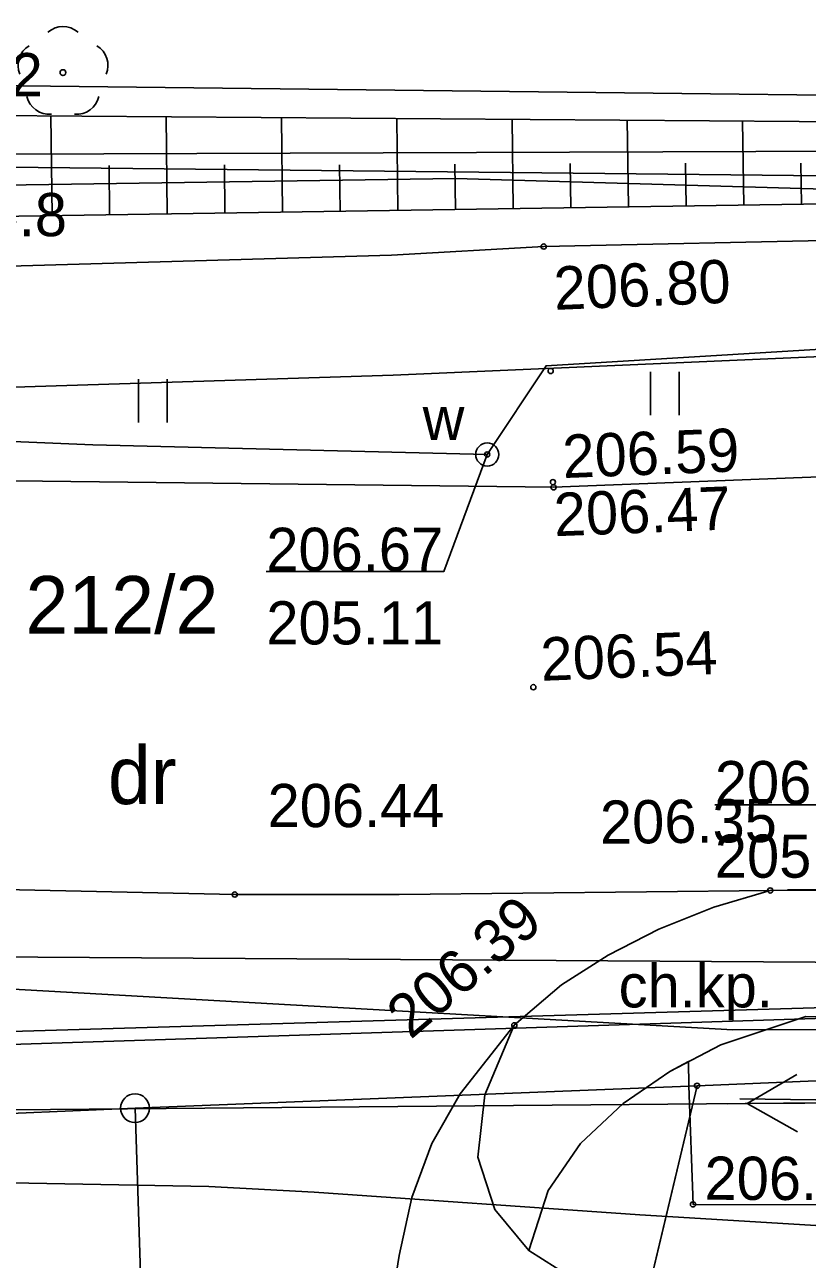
# Model space of a CAD drawing. Extents: x 6512400 to 6513200, y 6022500 to 6022750.
# Drawn here: x 6512733.85 to 6512747.42, y 6022670.32 to 6022691.75 of the extents above; entities that cross this region are included whole.
import ezdxf

# ---------------------------------------------------------------- set-up
doc = ezdxf.new("R2010")
doc.units = 0
for name, color, linetype in [('202-punkt graniczny', 7, 'Continuous'), ('203-punkt graniczny', 7, 'Continuous'), ('210-oznaczenie konturu użytku gruntowego', 7, 'Continuous'), ('211-numer działki ewidencyjnej', 7, 'Continuous'), ('216-obręb ewidencyjny', 7, 'Continuous'), ('218-kontur użytku gruntowego', 7, 'Continuous'), ('219-działka ewidencyjna', 7, 'Continuous'), ('820-Skarpa nieumocniona', 7, 'Continuous'), ('823-Szczyt skarpy nieumocninej', 7, 'Continuous'), ('824-Podnóże skarpy nieumocninej', 7, 'Continuous'), ('903-Żywopłot', 7, 'Continuous'), ('940-Trawnik symb. poj.', 7, 'Continuous'), ('chodnik', 7, 'Continuous'), ('chodnik (powierzchnia)', 7, 'Continuous'), ('chodnik (powierzchnia)-Atr17', 7, 'Continuous'), ('drzewo liściaste (punkt)', 7, 'Continuous'), ('inny obiekt zagospodarowania terenu', 7, 'Continuous'), ('jezdnia (powierzchnia)', 7, 'Continuous'), ('krawężnik (linia)', 7, 'Continuous'), ('przewód elektroenergetyczny (linia)', 7, 'Continuous'), ('przewód elektroenergetyczny niskiego napięcia (linia)', 7, 'Continuous'), ('przewód elektroenergetyczny niskiego napięcia (linia) - symbol', 7, 'Continuous'), ('przewód kanalizacyjny (linia)', 7, 'Continuous'), ('przewód telekomunikacyjny (linia)', 7, 'Continuous'), ('przewód wodociągowy (linia)', 7, 'Continuous'), ('punkt o określonej wysokości (sieć kanalizacyjna)-Atr2', 7, 'Continuous'), ('punkt o określonej wysokości (sieć kanalizacyjna)-Atr3', 7, 'Continuous'), ('punkt o określonej wysokości (sieć wodociągowa)', 7, 'Continuous'), ('punkt o określonej wysokości (sieć wodociągowa)-Atr2', 7, 'Continuous'), ('punkt o określonej wysokości (sieć wodociągowa)-Atr3', 7, 'Continuous'), ('punkt wysokościowy naturalny-Atr2', 7, 'Continuous'), ('punkt wysokościowy sztuczny', 7, 'Continuous'), ('punkt wysokościowy sztuczny-Atr2', 7, 'Continuous'), ('zasuwa - siec wodociągowa (punkt)', 7, 'Continuous'), ('zasuwa - siec wodociągowa (punkt)-Atr17', 7, 'Continuous')]:
    doc.layers.add(name, color=color, linetype=linetype)

# ---------------------------------------------------------------- blocks, each defined once
blk = doc.blocks.new('203')
blk.add_circle((0, 0), 0.045)
blk = doc.blocks.new('202')
blk.add_circle((0, 0), 0.25)
blk = doc.blocks.new('OP021')
blk.add_circle((0, 0), 0.05)
for centre, start, end in [((0, 0.4), 49.272, 130.728), ((-0.38, 0.124), 121.308, 202.548), ((0.38, 0.124), 337.452, 58.692), ((-0.235, -0.324), 193.221, 274.871), ((0.235, -0.324), 265.129, 346.779)]:
    blk.add_arc(centre, 0.4, start, end)
blk = doc.blocks.new('940P')
for p, q in [((-0.25, -0.375), (-0.25, 0.375)), ((0.25, -0.375), (0.25, 0.375))]:
    blk.add_line(p, q)
blk = doc.blocks.new('PW01')
blk.add_circle((0, 0), 0.045)
blk = doc.blocks.new('US25')
blk.add_circle((0, 0), 0.2)
blk = doc.blocks.new('PW02')
blk.add_circle((0, 0), 0.045)
blk = doc.blocks.new('PE04')
for p, q in [((4.65, 0), (3.784, 0.5)), ((0.65, 0), (0, 0)), ((0.65, 0), (1.65, 0)), ((1.65, 0), (2.65, 0)), ((2.65, 0), (3.65, 0)), ((3.65, 0), (4.65, 0)), ((4.65, 0), (3.784, -0.5)), ((4.65, 0), (5, 0))]:
    blk.add_line(p, q)

msp = doc.modelspace()

# ---------------------------------------------------------------- linework, layer by layer
at = {"layer": '216-obręb ewidencyjny'}
for points in [[(6512688.62, 6022674.91), (6512702.58, 6022674.18), (6512725.78, 6022672.95), (6512730.35, 6022672.71), (6512735.76, 6022672.94), (6512745.51, 6022673.33), (6512754.87, 6022673.72), (6512768.24, 6022674.27), (6512785.56, 6022674.74), (6512790.49, 6022674.74), (6512796.96, 6022674.74), (6512801.96, 6022670.34), (6512828.67, 6022670.98), (6512833.61, 6022675.02), (6512836.69, 6022675.17), (6512851.94, 6022675.93)], [(6512785.56, 6022674.74), (6512768.24, 6022674.27), (6512754.87, 6022673.72), (6512745.51, 6022673.33), (6512735.76, 6022672.94), (6512730.35, 6022672.71), (6512725.78, 6022672.95), (6512702.575, 6022674.177)]]:
    msp.add_lwpolyline(points, dxfattribs=at)
at = {"layer": '218-kontur użytku gruntowego'}
for points in [[(6512706.4, 6022691.01), (6512787.08, 6022690.07)], [(6512787.08, 6022690.07), (6512706.4, 6022691.01)], [(6512754.87, 6022673.72), (6512745.51, 6022673.33)], [(6512745.51, 6022673.33), (6512754.87, 6022673.72)], [(6512745.51, 6022673.33), (6512735.76, 6022672.94)], [(6512735.76, 6022672.94), (6512745.51, 6022673.33)], [(6512745.51, 6022673.33), (6512741.4, 6022656.05)], [(6512741.4, 6022656.05), (6512745.51, 6022673.33)], [(6512735.76, 6022672.94), (6512730.35, 6022672.71)], [(6512730.35, 6022672.71), (6512735.76, 6022672.94)], [(6512735.76, 6022672.94), (6512736.07, 6022663.44)], [(6512736.07, 6022663.44), (6512735.76, 6022672.94)]]:
    msp.add_lwpolyline(points, dxfattribs=at)
at = {"layer": '219-działka ewidencyjna'}
for points in [[(6512706.4, 6022691.01), (6512787.08, 6022690.07)], [(6512754.87, 6022673.72), (6512745.51, 6022673.33)], [(6512745.51, 6022673.33), (6512735.76, 6022672.94)], [(6512745.51, 6022673.33), (6512739.15, 6022646.62)], [(6512730.35, 6022672.71), (6512735.76, 6022672.94)], [(6512735.76, 6022672.94), (6512736.07, 6022663.44)]]:
    msp.add_lwpolyline(points, dxfattribs=at)
at = {"layer": '820-Skarpa nieumocniona'}
for p, q in [((6512734.32, 6022688.44), (6512734.3, 6022690.17)), ((6512736.32, 6022688.47), (6512736.3, 6022690.16)), ((6512738.32, 6022688.5), (6512738.3, 6022690.14)), ((6512740.32, 6022688.53), (6512740.3, 6022690.13)), ((6512742.32, 6022688.56), (6512742.3, 6022690.11)), ((6512744.32, 6022688.59), (6512744.3, 6022690.1)), ((6512746.32, 6022688.62), (6512746.3, 6022690.08)), ((6512735.32, 6022688.45), (6512735.31, 6022689.31)), ((6512737.32, 6022688.48), (6512737.31, 6022689.32)), ((6512739.32, 6022688.51), (6512739.31, 6022689.32)), ((6512741.32, 6022688.54), (6512741.31, 6022689.33)), ((6512743.32, 6022688.57), (6512743.31, 6022689.34)), ((6512745.32, 6022688.6), (6512745.31, 6022689.35)), ((6512747.32, 6022688.63), (6512747.31, 6022689.35))]:
    msp.add_line(p, q, dxfattribs=at)
at = {"layer": '823-Szczyt skarpy nieumocninej'}
msp.add_lwpolyline([(6512754.81, 6022689.02), (6512750.38, 6022688.68), (6512731.85, 6022688.4), (6512721.27, 6022688.58), (6512714.51, 6022690.92)], dxfattribs=at)
at = {"layer": '824-Podnóże skarpy nieumocninej'}
msp.add_lwpolyline([(6512714.51, 6022690.92), (6512719.59, 6022690.77), (6512731.72, 6022690.19), (6512750.39, 6022690.05), (6512754.81, 6022689.02)], dxfattribs=at)
at = {"layer": '903-Żywopłot'}
msp.add_lwpolyline([(6512750.46, 6022689.1), (6512732.44, 6022689.29)], dxfattribs=at)
at = {"layer": 'chodnik'}
msp.add_lwpolyline([(6512768.44, 6022668.05), (6512768.21, 6022674.06), (6512768.22, 6022675.69), (6512769.23, 6022676.77), (6512761.81, 6022676.79), (6512762.96, 6022675.7), (6512762.9, 6022674.52), (6512762.83, 6022671.34), (6512755.26, 6022671.25), (6512745.44, 6022671.27), (6512745.37, 6022673.33), (6512745.36, 6022673.75), (6512745.04, 6022673.58), (6512744.23, 6022673.02), (6512743.49, 6022672.33), (6512742.93, 6022671.51), (6512742.59, 6022670.47), (6512743.54, 6022669.87)], dxfattribs=at)
at = {"layer": 'chodnik (powierzchnia)'}
for points in [[(6512786.39, 6022689.96), (6512786.43, 6022689.56), (6512785.75, 6022688.59), (6512780.55, 6022688.53), (6512773.92, 6022688.46), (6512772.96, 6022688.47), (6512771.38, 6022688.54), (6512759.61, 6022688.41), (6512758.59, 6022688.29), (6512753.64, 6022688.13), (6512742.85, 6022687.9), (6512740.21, 6022687.75), (6512727.76, 6022687.39)], [(6512770.26, 6022685.56), (6512768.81, 6022686.87), (6512761.83, 6022686.62), (6512760.89, 6022686.7), (6512759.88, 6022686.67), (6512758.73, 6022686.47), (6512753.37, 6022686.24), (6512740.24, 6022685.67), (6512727.63, 6022685.27)], [(6512747.4, 6022674.53), (6512745.92, 6022674.04), (6512745.04, 6022673.58), (6512744.23, 6022673.02), (6512743.49, 6022672.33), (6512742.93, 6022671.51), (6512742.59, 6022670.47), (6512742, 6022671.18), (6512741.71, 6022672.09), (6512741.83, 6022673.17), (6512742.34, 6022674.38), (6512743.16, 6022675.08), (6512743.97, 6022675.6), (6512744.85, 6022676.05), (6512745.8, 6022676.43), (6512746.78, 6022676.72)], [(6512747.08, 6022676.73), (6512757.48, 6022676.77), (6512761.81, 6022676.79), (6512762.96, 6022675.7), (6512762.9, 6022674.52), (6512757.26, 6022674.48), (6512747.4, 6022674.53)]]:
    msp.add_lwpolyline(points, dxfattribs=at)
at = {"layer": 'inny obiekt zagospodarowania terenu'}
msp.add_lwpolyline([(6512746.25, 6022673.1), (6512762.53, 6022672.89)], dxfattribs=at)
at = {"layer": 'jezdnia (powierzchnia)'}
for points in [[(6512707.74, 6022685), (6512715.41, 6022684.53), (6512729.72, 6022683.88), (6512743.02, 6022683.72), (6512757.15, 6022684.27)], [(6512707.08, 6022677.87), (6512714.85, 6022677.5), (6512727.62, 6022676.91), (6512733.49, 6022676.74), (6512737.49, 6022676.65), (6512740.34, 6022676.65), (6512746.78, 6022676.72), (6512757.48, 6022676.77)], [(6512740.11, 6022668.94), (6512740.34, 6022670.38), (6512740.56, 6022671.39), (6512740.91, 6022672.33), (6512741.4, 6022673.19), (6512742.34, 6022674.38), (6512743.16, 6022675.08), (6512743.97, 6022675.6), (6512744.85, 6022676.05), (6512745.8, 6022676.43), (6512746.78, 6022676.72), (6512740.34, 6022676.65), (6512737.49, 6022676.65), (6512733.49, 6022676.74)]]:
    msp.add_lwpolyline(points, dxfattribs=at)
at = {"layer": 'krawężnik (linia)'}
for points in [[(6512757.15, 6022684.27), (6512743.02, 6022683.72), (6512729.72, 6022683.88), (6512715.41, 6022684.53), (6512707.74, 6022685)], [(6512707.08, 6022677.87), (6512714.85, 6022677.5), (6512727.62, 6022676.91), (6512733.49, 6022676.74), (6512737.49, 6022676.65), (6512740.34, 6022676.65), (6512746.78, 6022676.72), (6512757.48, 6022676.77)], [(6512733.49, 6022676.74), (6512737.49, 6022676.65), (6512740.34, 6022676.65), (6512746.78, 6022676.72), (6512745.8, 6022676.43), (6512744.85, 6022676.05), (6512743.97, 6022675.6), (6512743.16, 6022675.08), (6512742.34, 6022674.38), (6512741.4, 6022673.19), (6512740.91, 6022672.33), (6512740.56, 6022671.39), (6512740.34, 6022670.38), (6512740.11, 6022668.94)]]:
    msp.add_lwpolyline(points, dxfattribs=at)
msp.add_lwpolyline([(6512742.34, 6022674.38), (6512741.83, 6022673.17), (6512741.71, 6022672.09), (6512742, 6022671.18), (6512742.59, 6022670.47), (6512743.54, 6022669.87), (6512744.61, 6022669.47), (6512743.66, 6022665.57), (6512742.75, 6022665.44), (6512741.78, 6022665.16), (6512740.87, 6022664.67), (6512740.14, 6022663.96), (6512739.53, 6022663.03), (6512739.77, 6022665.13), (6512739.93, 6022667.1), (6512740.11, 6022668.94), (6512740.34, 6022670.38), (6512740.56, 6022671.39), (6512740.91, 6022672.33), (6512741.4, 6022673.19)], close=True, dxfattribs=at)
at = {"layer": 'przewód elektroenergetyczny (linia)'}
for points in [[(6512731.37, 6022676.71), (6512731.37, 6022675.58), (6512748.46, 6022675.47), (6512780.13, 6022675.56), (6512787.87, 6022675.5)], [(6512702.569, 6022673.878), (6512710.28, 6022673.25), (6512716.66, 6022675.97), (6512746.13, 6022674.3), (6512752.79, 6022674.32), (6512760.61, 6022675.35), (6512763.38, 6022676.06), (6512798.79, 6022676.04)], [(6512702.603, 6022675.567), (6512731.84, 6022674.22), (6512765.79, 6022675.22), (6512787.87, 6022675.5)]]:
    msp.add_lwpolyline(points, dxfattribs=at)
at = {"layer": 'przewód elektroenergetyczny niskiego napięcia (linia)'}
for points in [[(6512782.09, 6022689.68), (6512702.887, 6022689.392)], [(6512702.887, 6022689.392), (6512782.09, 6022689.68)], [(6512719.56, 6022672.79), (6512751.03, 6022673.06)]]:
    msp.add_lwpolyline(points, dxfattribs=at)
at = {"layer": 'przewód kanalizacyjny (linia)'}
msp.add_lwpolyline([(6512716.83, 6022672.25), (6512720.83, 6022672.11), (6512730.47, 6022671.7), (6512737.04, 6022671.58), (6512738.87, 6022671.48), (6512744.52, 6022671.09), (6512750.15, 6022670.75), (6512752.63, 6022670.67), (6512753.2, 6022670.48)], dxfattribs=at)
at = {"layer": 'przewód telekomunikacyjny (linia)'}
msp.add_lwpolyline([(6512786.53, 6022688.5), (6512773.43, 6022688.9), (6512751.33, 6022688.79), (6512741.32, 6022689.08), (6512718.97, 6022688.75), (6512713.12, 6022690.07), (6512711.25, 6022690.1), (6512706.82, 6022689.08), (6512704.98, 6022689.07)], dxfattribs=at)
at = {"layer": 'przewód wodociągowy (linia)'}
for points in [[(6512777.27, 6022686.75), (6512776.94, 6022686.76), (6512762.32, 6022687.01), (6512742.89, 6022685.83), (6512741.87, 6022684.29)], [(6512702.822, 6022686.219), (6512712.1, 6022685.41), (6512735.03, 6022684.46), (6512741.87, 6022684.29)], [(6512702.579, 6022674.359), (6512731.63, 6022673.98), (6512765.81, 6022675.09), (6512780.05, 6022675.09), (6512787.64, 6022675.26)]]:
    msp.add_lwpolyline(points, dxfattribs=at)
at = {"layer": 'punkt o określonej wysokości (sieć kanalizacyjna)-Atr2'}
msp.add_lwpolyline([(6512750.37, 6022677.15), (6512748.96, 6022678.21), (6512745.819, 6022678.21)], dxfattribs=at)
at = {"layer": 'punkt o określonej wysokości (sieć wodociągowa)-Atr2'}
msp.add_lwpolyline([(6512741.87, 6022684.29), (6512741.12, 6022682.26), (6512738.038, 6022682.26)], dxfattribs=at)

# ---------------------------------------------------------------- block references
at = {"layer": '202-punkt graniczny'}
msp.add_blockref('202', (6512735.76, 6022672.94), dxfattribs=at)
at = {"layer": '203-punkt graniczny'}
msp.add_blockref('203', (6512745.51, 6022673.33), dxfattribs=at)
at = {"layer": '940-Trawnik symb. poj.'}
for p in [(6512744.95, 6022685.35), (6512736.07, 6022685.22)]:
    msp.add_blockref('940P', p, dxfattribs=at)
at = {"layer": 'drzewo liściaste (punkt)'}
msp.add_blockref('OP021', (6512734.51, 6022690.92), dxfattribs=at)
at = {"layer": 'przewód elektroenergetyczny niskiego napięcia (linia) - symbol', "rotation": -179.50800000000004}
msp.add_blockref('PE04', (6512751.03, 6022673.06), dxfattribs=at)
at = {"layer": 'punkt o określonej wysokości (sieć wodociągowa)'}
msp.add_blockref('PW01', (6512742.97, 6022685.74), dxfattribs=at)
at = {"layer": 'punkt o określonej wysokości (sieć wodociągowa)', "rotation": -0.586}
msp.add_blockref('PW01', (6512741.87, 6022684.29), dxfattribs=at)
at = {"layer": 'punkt wysokościowy sztuczny'}
for p in [(6512742.85, 6022687.9), (6512743.01, 6022683.81), (6512743.02, 6022683.72), (6512742.67, 6022680.25), (6512737.49, 6022676.65), (6512746.78, 6022676.72), (6512742.34, 6022674.38), (6512745.44, 6022671.27)]:
    msp.add_blockref('PW02', p, dxfattribs=at)
at = {"layer": 'zasuwa - siec wodociągowa (punkt)', "rotation": -0.586}
msp.add_blockref('US25', (6512741.87, 6022684.29), dxfattribs=at)

# ---------------------------------------------------------------- texts
at = {"layer": '210-oznaczenie konturu użytku gruntowego'}
msp.add_text('dr', height=1, dxfattribs=at).set_placement((6512735.29, 6022678.22))
at = {"layer": '211-numer działki ewidencyjnej'}
msp.add_text('212/2', height=1, dxfattribs=at).set_placement((6512733.86, 6022681.18))
at = {"layer": 'chodnik (powierzchnia)-Atr17'}
msp.add_text('ch.kp.', height=0.75, dxfattribs=at).set_placement((6512744.15, 6022674.69))
at = {"layer": 'punkt o określonej wysokości (sieć kanalizacyjna)-Atr2'}
msp.add_text('206.36', height=0.75, dxfattribs=at).set_placement((6512745.819, 6022678.218))
at = {"layer": 'punkt o określonej wysokości (sieć kanalizacyjna)-Atr3'}
msp.add_text('205.49', height=0.75, dxfattribs=at).set_placement((6512745.819, 6022676.942))
at = {"layer": 'punkt o określonej wysokości (sieć wodociągowa)-Atr2'}
msp.add_text('206.67', height=0.75, dxfattribs=at).set_placement((6512738.038, 6022682.268))
at = {"layer": 'punkt o określonej wysokości (sieć wodociągowa)-Atr3'}
msp.add_text('205.11', height=0.75, dxfattribs=at).set_placement((6512738.038, 6022680.992))
at = {"layer": 'punkt wysokościowy naturalny-Atr2'}
for s, p in [('206.2', (6512731.65, 6022690.51)), ('206.8', (6512732.07, 6022688.08))]:
    msp.add_text(s, height=0.75, dxfattribs=at).set_placement(p)
at = {"layer": 'punkt wysokościowy sztuczny-Atr2'}
for s, rotation, p in [('206.80', 2.382, (6512743.04, 6022686.8)), ('206.59', 2.229, (6512743.19, 6022683.88)), ('206.47', 2.229, (6512743.04, 6022682.87)), ('206.54', 2.229, (6512742.81, 6022680.36)), ('206.35', 0.622, (6512743.83, 6022677.53)), ('206.39', 40.486, (6512740.54, 6022674.12)), ('206.50', 359.883, (6512745.64, 6022671.35))]:
    msp.add_text(s, height=0.75, rotation=rotation, dxfattribs=at).set_placement(p)
msp.add_text('206.44', height=0.75, dxfattribs=at).set_placement((6512738.06, 6022677.82))
at = {"layer": 'zasuwa - siec wodociągowa (punkt)-Atr17'}
msp.add_text('w', height=0.75, dxfattribs=at).set_placement((6512740.75, 6022684.54))

doc.saveas('drawing.dxf')
